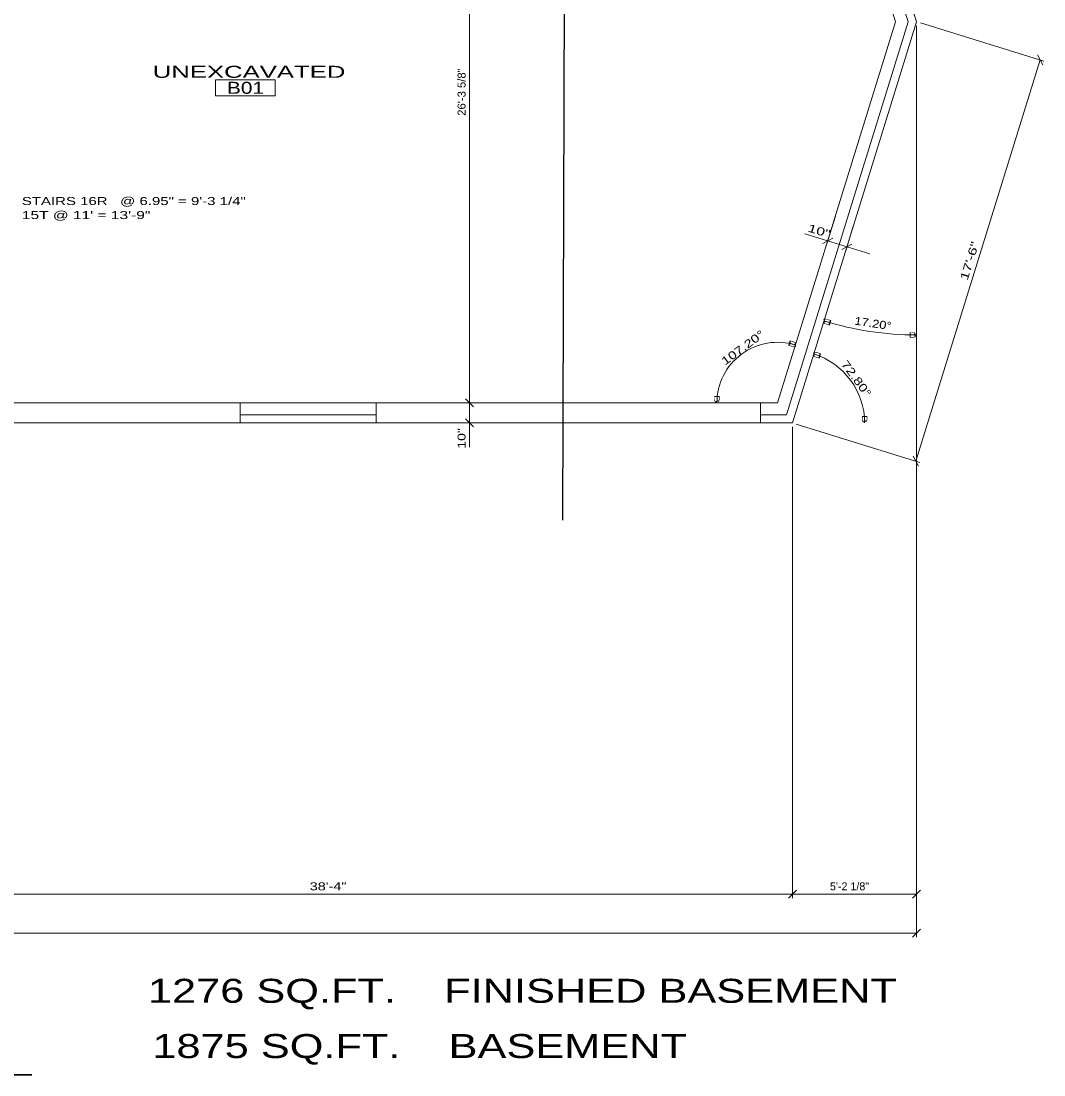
# Model space of a CAD drawing. Extents: x 7 to 126, y 6 to 93.
# Drawn here: x 83.75 to 126.35, y 7.2 to 51.09 of the extents above; entities that cross this region are included whole.
import ezdxf
from ezdxf.enums import TextEntityAlignment as Align

# ---------------------------------------------------------------- set-up
doc = ezdxf.new("R2010")
doc.units = 0
doc.header["$LTSCALE"] = 0.13
for name, color, linetype, lineweight in [('13', 7, 'Continuous', 13), ('14', 7, 'Continuous', 13), ('15', 7, 'Continuous', 13), ('40', 7, 'Continuous', 13), ('45', 7, 'Continuous', 13), ('47', 7, 'Continuous', 35), ('50', 7, 'Continuous', 13), ('7', 7, 'Continuous', 13)]:
    doc.layers.add(name, color=color, linetype=linetype, lineweight=lineweight)
doc.layers.add('46', color=7, linetype='Continuous')

msp = doc.modelspace()

# ---------------------------------------------------------------- linework, layer by layer
at = {"layer": '13'}
for p, q in [((120.6983, 51.0685), (118.4133, 58.4502)), ((120.6983, 51.0685), (115.6266, 34.6845)), ((98.5521, 34.6845), (92.8724, 34.6845)), ((92.9062, 34.6845), (98.5521, 34.6845)), ((115.6266, 34.6845), (114.5521, 34.6845))]:
    msp.add_line(p, q, dxfattribs=at)
at = {"layer": '14'}
for p, q in [((113.4884, 75.4873), (121.0473, 51.0685)), ((121.0473, 51.0685), (115.8724, 34.3511))]:
    msp.add_line(p, q, dxfattribs=at)
msp.add_lwpolyline([(115.8724, 34.3511), (77.539, 34.3511), (75.8724, 37.2379), (59.2057, 37.2379), (57.539, 34.3511), (40.8724, 34.3511), (16.7057, 76.209), (22.539, 86.3127), (34.2057, 86.3127), (44.2057, 68.9922), (60.8724, 68.9922)], dxfattribs=at)
at = {"layer": '15'}
for p, q in [((120.1749, 51.0685), (116.9497, 61.4873)), ((120.1749, 51.0685), (115.258, 35.1845)), ((92.8724, 34.3511), (92.8724, 35.1845)), ((98.5415, 34.3658), (98.5415, 35.1845)), ((114.5415, 34.3658), (114.5415, 35.1845))]:
    msp.add_line(p, q, dxfattribs=at)
msp.add_lwpolyline([(115.258, 35.1845), (78.0202, 35.1845), (76.7384, 37.4046)], dxfattribs=at)
at = {"layer": '40', "lineweight": 25}
msp.add_line((106.4376, 80.4582), (106.3021, 30.3021), dxfattribs=at)
at = {"layer": '45'}
msp.add_lwpolyline([(91.8438, 47.9752), (94.3289, 47.9752), (94.3289, 48.6458), (91.8438, 48.6458)], close=True, dxfattribs=at)
at = {"layer": '47'}
msp.add_line((64.285, 7.195), (84.1994, 7.195), dxfattribs=at)
at = {"layer": '50'}
for p, q in [((102.4271, 61.4873), (102.4271, 35.1845)), ((121.2065, 51.0192), (126.3507, 49.4268)), ((121.0473, 50.9019), (121.0473, 14.5521)), ((126.0816, 49.6846), (126.3014, 49.2676)), ((121.0166, 32.7587), (126.1915, 49.4761)), ((117.6672, 42.9673), (117.2984, 41.7759)), ((119.099, 41.393), (116.3924, 42.2309)), ((118.4105, 42.5506), (118.0944, 41.5295)), ((117.5562, 42.0451), (117.1392, 41.8252)), ((117.9352, 41.5788), (118.3522, 41.7987)), ((102.4271, 33.3511), (102.4271, 36.1845)), ((96.8057, 35.1845), (102.5938, 35.1845)), ((102.5938, 35.0178), (102.2604, 35.3511)), ((102.5938, 35.0178), (102.2604, 35.3511)), ((96.8724, 34.3511), (102.5938, 34.3511)), ((102.2604, 34.5178), (102.5938, 34.1845)), ((116.0316, 34.3019), (121.1758, 32.7095)), ((115.8724, 34.1845), (115.8724, 14.5521)), ((121.1265, 32.5502), (120.9067, 32.9672)), ((77.539, 14.7188), (115.8724, 14.7188)), ((116.039, 14.8854), (115.7057, 14.5521)), ((115.7057, 14.5521), (116.039, 14.8854)), ((115.7057, 14.5521), (116.039, 14.8854)), ((115.8724, 14.7188), (115.8724, 14.8854)), ((115.8724, 14.7188), (121.0473, 14.7188)), ((121.2139, 14.8854), (120.8806, 14.5521)), ((121.0473, 14.5521), (121.0473, 12.9271)), ((121.2139, 13.2604), (120.8806, 12.9271)), ((121.0473, 13.0938), (16.7057, 13.0938))]:
    msp.add_line(p, q, dxfattribs=at)
for centre, radius, start, end in [((121.0473, 51.0685), 13.0482, 252.8, 270), ((115.258, 35.1845), 2.5288, 72.79989, 180), ((115.8724, 34.3511), 3.0099, 0, 72.79994)]:
    msp.add_arc(centre, radius, start, end, dxfattribs=at)
at = {"layer": '7'}
msp.add_line((121.0473, 51.0685), (115.8724, 34.3511), dxfattribs=at)
msp.add_lwpolyline([(115.8724, 34.3511), (77.539, 34.3511), (75.8724, 37.2379), (59.2057, 37.2379), (57.539, 34.3511), (40.8724, 34.3511), (16.7057, 76.209), (22.539, 86.3127), (34.2057, 86.3127), (44.2057, 68.9922), (60.8724, 68.9922), (64.2057, 63.2187), (65.039, 63.2187), (75.039, 63.2187), (80.039, 71.8789), (96.7057, 71.8789), (98.789, 75.4873), (113.4884, 75.4873), (121.0473, 51.0685)], dxfattribs=at)

# ---------------------------------------------------------------- texts
at = {"layer": '45'}
for s, width, p in [('     UNEXCAVATED    ', 1.6, (93.0937, 48.7292)), (' B01 ', 1.3, (93.0937, 48.0625))]:
    msp.add_text(s, height=0.5, dxfattribs=dict(at, width=width)).set_placement(p, align=Align.CENTER)
at = {"layer": '46', "width": 1.35}
for s, p in [('1276 SQ.FT.    FINISHED BASEMENT', (89.0295, 10.1983)), ('1875 SQ.FT.    BASEMENT', (89.2136, 7.8973))]:
    msp.add_text(s, height=1, dxfattribs=at).set_placement(p)
at = {"layer": '50'}
for s, rotation, width, p in [('26\'-3 5/8"', 90, 1.05, (102.2604, 47.1496)), ('10"', 342.8, 1.45, (116.4884, 42.3337)), ('17\'-6"', 72.8, 1.45, (123.1677, 40.2716)), ('17.20°', 351.4, 1.2, (118.4411, 38.4531)), ('107.20°', 36.4, 1.35, (113.0684, 36.7413)), ('72.80°', 306.4, 1.35, (117.8865, 36.8006)), ('10"', 90, 1.3, (102.2604, 33.2848))]:
    msp.add_text(s, height=0.3333, rotation=rotation, dxfattribs=dict(at, width=width)).set_placement(p)
for s, width, p in [('STAIRS 16R   @ 6.95" = 9\'-3 1/4"  ', 1.4, (83.7784, 43.4296)), ('15T @ 11\' = 13\'-9"', 1.45, (83.7784, 42.8463)), ('38\'-4"', 1.35, (95.7687, 14.8854))]:
    msp.add_text(s, height=0.3333, dxfattribs=dict(at, width=width)).set_placement(p)
for rotation, width, p in [(162.8, 2.05, (117.1559, 38.7303)), (342.8, 2.05, (116.0386, 37.4737)), (162.8, 2.05, (116.7296, 37.3529)), (270, 1.7, (112.6181, 35.1845)), (270, 1.7, (118.7712, 34.3511))]:
    msp.add_text('B', height=0.2222, rotation=rotation, dxfattribs=dict(at, width=width)).set_placement(p, align=Align.RIGHT)
at = {"layer": '50', "width": 1.7}
msp.add_text('B', height=0.2222, dxfattribs=at).set_placement((121.0473, 37.9092), align=Align.RIGHT)
at = {"layer": '50'}
msp.add_text('5\'-2 1/8"', height=0.3333, dxfattribs=at).set_placement((117.4388, 14.8854))

doc.saveas('drawing.dxf')
